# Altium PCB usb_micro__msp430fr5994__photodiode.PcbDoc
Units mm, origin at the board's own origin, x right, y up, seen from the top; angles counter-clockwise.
Board outline 40 x 21 mm, 2 copper layers (Top, Bottom), stack 0 mm thick; 25 components, 16 nets, 136 pads, 47 vias.
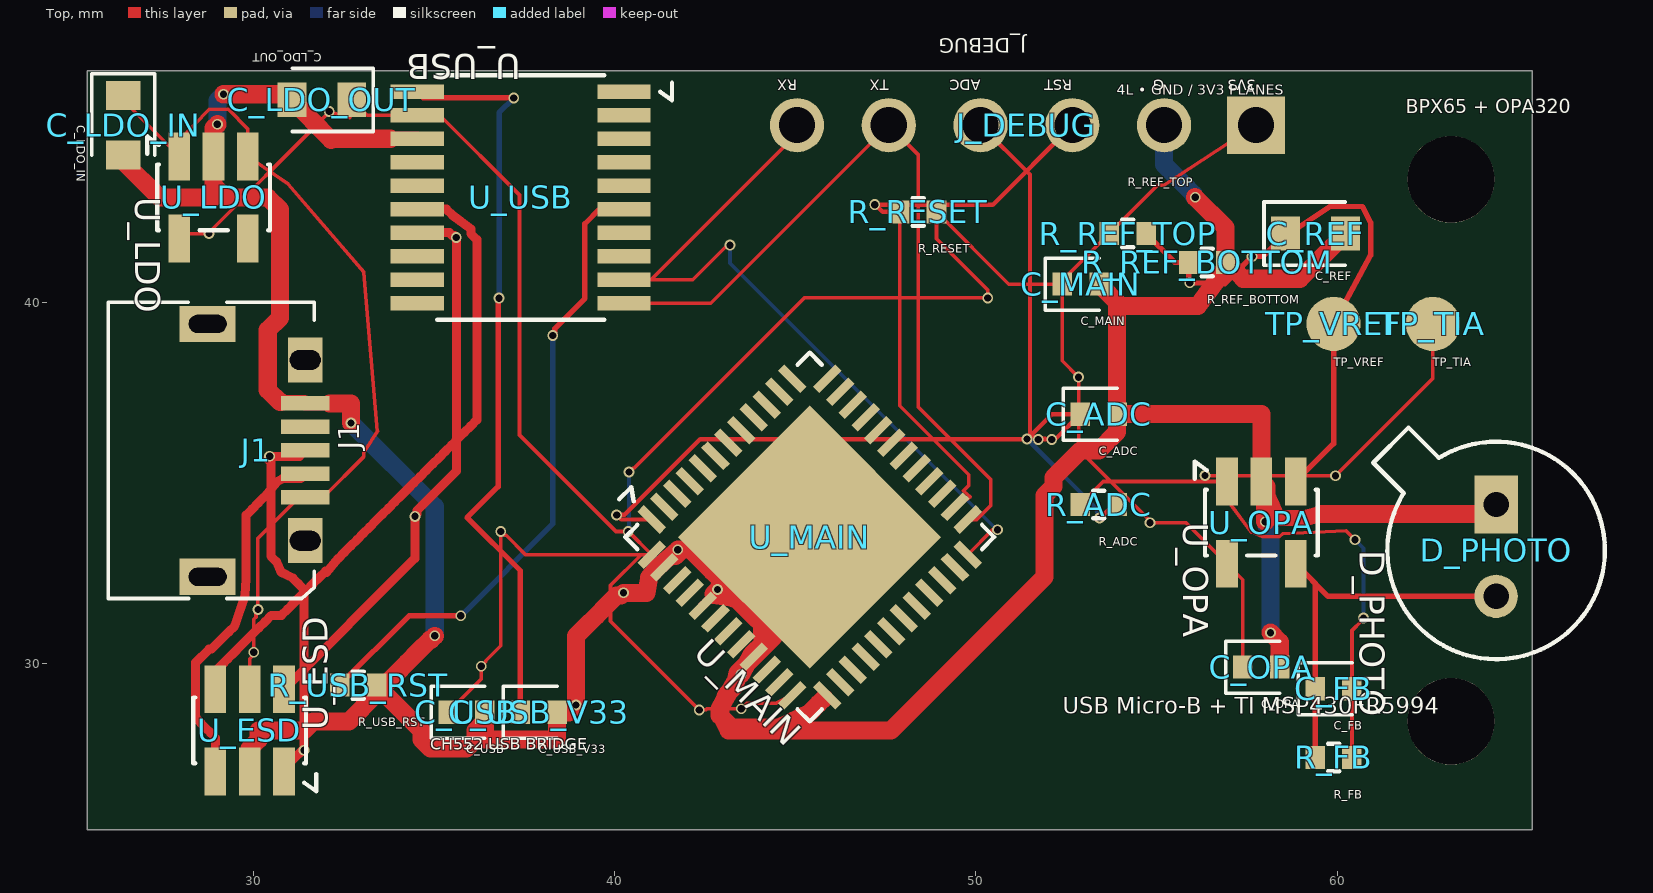
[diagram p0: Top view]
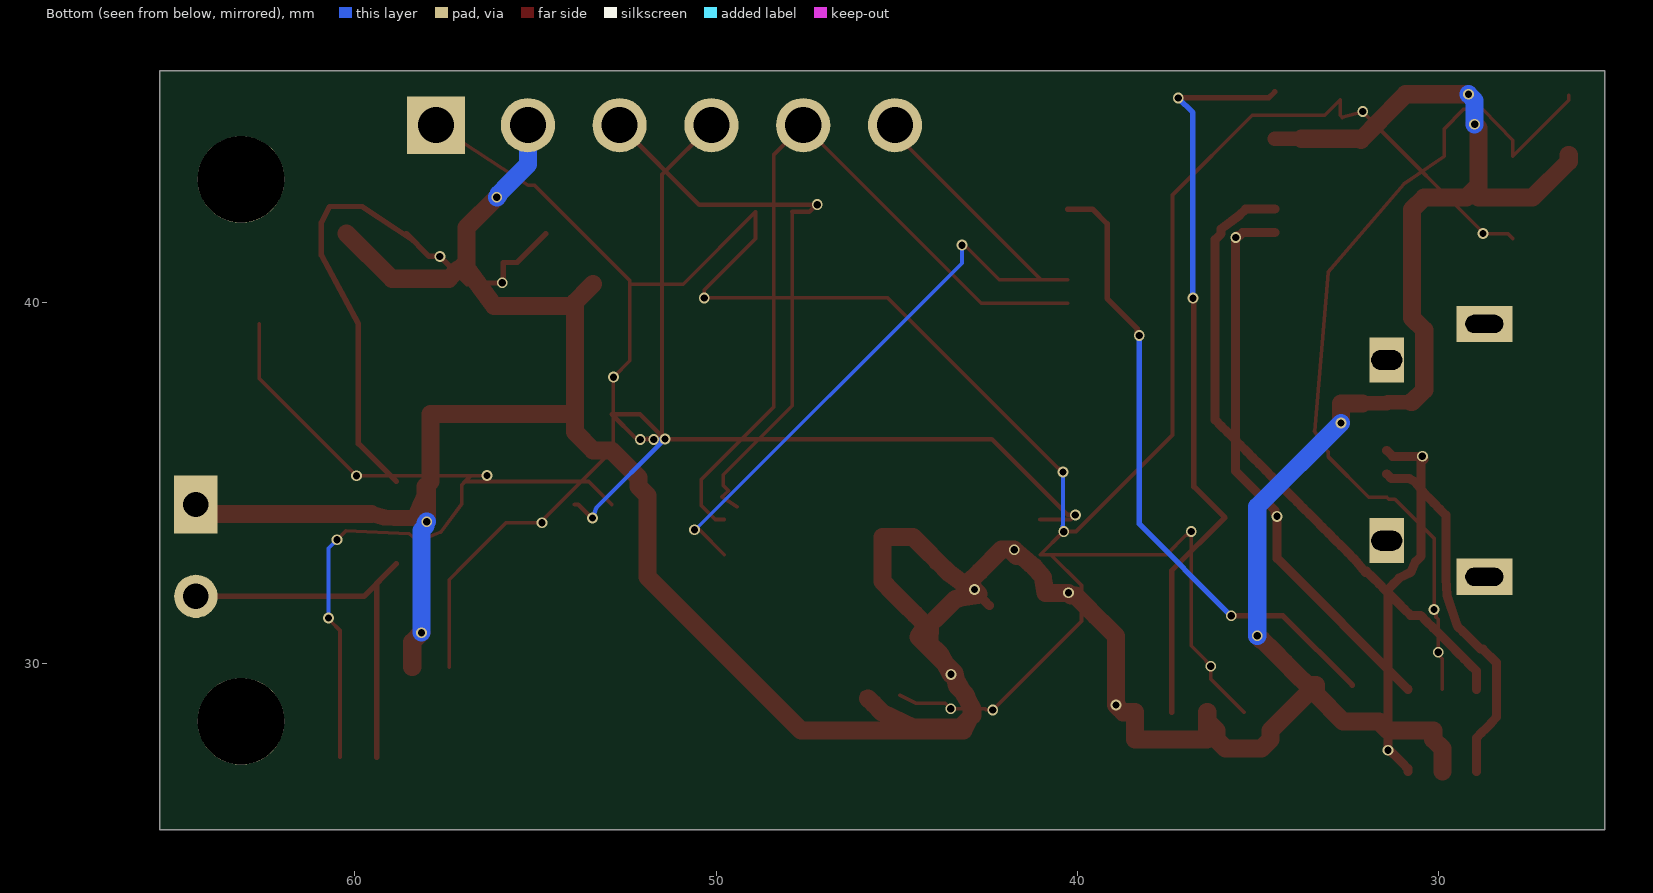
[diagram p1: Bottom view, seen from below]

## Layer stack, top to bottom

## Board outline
25.4,46.4 65.4,46.4 65.4,25.4 25.4,25.4

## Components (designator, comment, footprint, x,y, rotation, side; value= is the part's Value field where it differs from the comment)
C_ADC "" TSCIRCUIT-1.5600x0.6400mm 53.4,36.9 r0 top
C_FB "" TSCIRCUIT-1.5600x0.6400mm 59.9,29.3 r0 top
C_LDO_IN "" TSCIRCUIT-0.9500x2.4500mm 26.4,44.9 r270 top
C_LDO_OUT "" TSCIRCUIT-2.4500x0.9500mm 31.9,45.6 r180 top
C_MAIN "" TSCIRCUIT-1.5600x0.6400mm 52.9,40.5 r0 top
C_OPA "" TSCIRCUIT-1.5600x0.6400mm 57.9,29.9 r0 top
C_REF "" TSCIRCUIT-2.4500x0.9500mm 59.4,41.9 r0 top
C_USB "" TSCIRCUIT-1.5600x0.6400mm 35.9,28.65 r0 top
C_USB_V33 "" TSCIRCUIT-1.5600x0.6400mm 37.9,28.65 r0 top
D_PHOTO "" TSCIRCUIT-1.2000x3.9400mm 64.4,33.23 r270 top
J1 "" TSCIRCUIT-4.1500x8mm 30.037,35.9 r90 top
J_DEBUG "" TSCIRCUIT-14.2000x1.5000mm 51.4,44.9 r180 top
R_ADC "" TSCIRCUIT-1.5600x0.6400mm 53.4,34.4 r0 top
R_FB "" TSCIRCUIT-1.5600x0.6400mm 59.9,27.4 r0 top
R_REF_BOTTOM "" TSCIRCUIT-1.5600x0.6400mm 56.4,41.1 r0 top
R_REF_TOP "" TSCIRCUIT-1.5600x0.6400mm 54.2,41.9 r0 top
R_RESET "" TSCIRCUIT-1.5600x0.6400mm 48.4,42.5 r0 top
R_USB_RST "" TSCIRCUIT-1.5600x0.6400mm 32.9,29.4 r0 top
TP_TIA "" TSCIRCUIT-1.5000x1.5000mm 62.65,39.4 r0 top
TP_VREF "" TSCIRCUIT-1.5000x1.5000mm 59.9,39.4 r0 top
U_ESD "" TSCIRCUIT-2.5000x3.6000mm#1 29.9,28.15 r90 top
U_LDO "" TSCIRCUIT-2.5000x3.6000mm#2 28.9,42.9 r270 top
U_MAIN "" TSCIRCUIT-9.5459x9.5459mm 45.4,33.5 r315 top
U_OPA "" TSCIRCUIT-2.5000x3.6000mm#2 57.9,33.9 r270 top
U_USB "" TSCIRCUIT-7.2000x6.2500mm 37.4,42.9 r180 top

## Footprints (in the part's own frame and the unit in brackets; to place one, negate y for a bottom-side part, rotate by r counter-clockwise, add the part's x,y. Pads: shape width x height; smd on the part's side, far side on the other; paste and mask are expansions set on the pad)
TSCIRCUIT-0.9500x2.4500mm [mm]
  rect 0.8x0.95 smd: 1(-0.825,0) 2(0.825,0)
  silkscreen extent -1.43,-0.87 0.82,0.87
TSCIRCUIT-1.2000x3.9400mm [mm]
  rect 1.6x1.2 hole 0.7: 1(-1.17,0)
  round 1.2 hole 0.7: 2(1.37,0)
  silkscreen extent -3.3,-3.4 3.11,3.01
TSCIRCUIT-1.5000x1.5000mm [mm]
  round 1.5 smd: 1(0,0)
TSCIRCUIT-1.5600x0.6400mm [mm]
  rect 0.54x0.64 smd: 1(-0.51,0) 2(0.51,0)
  silkscreen extent -0.98,-0.72 0.51,0.72
TSCIRCUIT-2.4500x0.9500mm [mm]
  rect 0.8x0.95 smd: 1(-0.825,0) 2(0.825,0)
  silkscreen extent -1.43,-0.87 0.82,0.87
TSCIRCUIT-2.5000x3.6000mm#1 [mm]
  rect 1.325x0.6 smd: 1(-1.137,-0.95) 2(-1.137,0) 3(-1.137,0.95) 4(1.138,0.95) 5(1.138,0) 6(1.138,-0.95)
  silkscreen extent -1.69,-1.84 0.91,1.56
TSCIRCUIT-2.5000x3.6000mm#2 [mm]
  rect 1.325x0.6 smd: 1(-1.137,-0.95) 2(-1.137,0) 3(-1.137,0.95) 4(1.138,0.95) 5(1.138,-0.95)
  silkscreen extent -1.69,-1.84 0.91,1.56
TSCIRCUIT-4.1500x8mm [mm]
  rect 0.4x1.35 smd: 1(-1.301,-1.4) 2(-0.65,-1.4) 3(0,-1.4) 4(0.65,-1.4) 5(1.3,-1.4)
  rect 1.25x0.95 hole 0.55 slot 0.85 at 90 deg: 6(2.5,-1.4) 7(-2.5,-1.4)
  rect 1x1.55 hole 0.5 slot 1.05 at 90 deg: 8(-3.5,1.3) 9(3.5,1.3)
  silkscreen extent -4.1,-1.65 4.1,4.05
TSCIRCUIT-7.2000x6.2500mm [mm]
  rect 1.475x0.4 smd: 1(-2.863,-2.925) 2(-2.863,-2.275) 3(-2.863,-1.625) 4(-2.863,-0.975) 5(-2.863,-0.325) 6(-2.863,0.325) 7(-2.863,0.975) 8(-2.863,1.625) 9(-2.863,2.275) 10(-2.863,2.925) 11(2.862,2.925) 12(2.862,2.275) 13(2.862,1.625) 14(2.862,0.975) 15(2.862,0.325) 16(2.862,-0.325) 17(2.862,-0.975) 18(2.862,-1.625) 19(2.862,-2.275) 20(2.862,-2.925)
  silkscreen extent -4.19,-3.38 2.31,3.38
TSCIRCUIT-9.5459x9.5459mm [mm]
  rect 0.875x0.25 smd: 1(-3.438,-2.75) 2(-3.438,-2.25) 3(-3.438,-1.75) 4(-3.438,-1.25) 5(-3.438,-0.75) 6(-3.438,-0.25) 7(-3.438,0.25) 8(-3.438,0.75) 9(-3.438,1.25) 10(-3.438,1.75) 11(-3.438,2.25) 12(-3.438,2.75) 25(3.438,2.75) 26(3.437,2.25) 27(3.437,1.75) 28(3.437,1.25) 29(3.438,0.75) 30(3.437,0.25) 31(3.437,-0.25) 32(3.437,-0.75) 33(3.438,-1.25) 34(3.437,-1.75) 35(3.437,-2.25) 36(3.437,-2.75)
  rect 0.25x0.875 smd: 13(-2.75,3.438) 14(-2.25,3.438) 15(-1.75,3.438) 16(-1.25,3.438) 17(-0.75,3.438) 18(-0.25,3.438) 19(0.25,3.438) 20(0.75,3.438) 21(1.25,3.438) 22(1.75,3.438) 23(2.25,3.438) 24(2.75,3.438) 37(2.75,-3.437) 38(2.25,-3.438) 39(1.75,-3.438) 40(1.25,-3.438) 41(0.75,-3.437) 42(0.25,-3.438) 43(-0.25,-3.438) 44(-0.75,-3.438) 45(-1.25,-3.437) 46(-1.75,-3.438) 47(-2.25,-3.438) 48(-2.75,-3.438)
  rect 5.15x5.15 smd: 49(0,0)
  silkscreen extent -4.47,-3.61 3.61,3.61
TSCIRCUIT-14.2000x1.5000mm [mm]
  rect 1.6x1.6 hole 1: 1(-6.35,0)
  round 1.5 hole 1: 2(-3.81,0) 3(-1.27,0) 4(1.27,0) 5(3.81,0) 6(6.35,0)

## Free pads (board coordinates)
  round 2.4 hole 2.4 unplated: NPTH-1(63.15,43.4) NPTH-2(63.15,28.4)

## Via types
v1: diameter 0.3, hole 0.2, Top to Bottom, 47 vias

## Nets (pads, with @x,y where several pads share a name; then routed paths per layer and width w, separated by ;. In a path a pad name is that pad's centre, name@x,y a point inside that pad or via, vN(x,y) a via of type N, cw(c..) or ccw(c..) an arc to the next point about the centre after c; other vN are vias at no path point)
".U_USB > .pin9 to .U_MAIN > .pin25": J_DEBUG.6 U_MAIN.25 U_USB.9 | length 22.1
  Top w0.1: v1(43.195,41.579) 43.193,41.577 43.118,41.577 42.166,40.625 U_USB.9 40.269,40.619 41.005,40.619 45.05,44.664 J_DEBUG.6 ; U_MAIN.25 50.461,33.7 v1(50.6,33.7)
  Bottom w0.1: v1(43.195,41.579) 43.195,41.081 50.576,33.7 v1(50.6,33.7)
".U_USB > .pin10 to .U_MAIN > .pin24": J_DEBUG.5 U_MAIN.24 U_USB.10 | length 21.9
  Top w0.1: U_USB.10 42.665,39.975 J_DEBUG.5 48.4,44.09 48.4,42.236 48.4,37.11 50.407,35.103 50.407,34.368 50.025,33.986 U_MAIN.24@49.775,33.986
ADC_IN: C_ADC.1 J_DEBUG.4 R_ADC.2 U_MAIN.1 | length 31.5
  Top w0.12: U_MAIN.1 40.18,33.986 v1(40.057,34.109) 40.065,34.117 40.275,34.117 42.368,36.21 v1(51.416,36.21) 51.423,36.218 52.106,36.9 C_ADC.1 ; J_DEBUG.4 51.496,43.534 51.496,36.416 51.496,36.291 v1(52.1,36.2) v1@52.2,36.21 ; v1(51.725,36.2) v1@52.2,36.21 ; v1(53.42,34.028) 53.394,34.086 53.399,34.007 53.399,33.983 53.817,34.4 R_ADC.2 ; v1@52.2,36.21 C_ADC.1 ; v1@52.2,36.21 C_ADC.1
  Bottom w0.12: v1(51.725,36.2) 51.422,36.204 53.31,34.317 v1(53.42,34.028)
GND: C_ADC.2 C_LDO_IN.2 C_LDO_OUT.2 C_MAIN.2 C_OPA.2 C_REF.2 C_USB.2 C_USB_V33.2 D_PHOTO.1 J1.5 J_DEBUG.2 R_REF_BOTTOM.2 R_USB_RST.2 U_ESD.2 U_LDO.2 U_MAIN.36 U_MAIN.40 U_MAIN.44 U_MAIN.47 U_MAIN.49 U_OPA.2 U_USB.18 | length 127.1
  Top w0.1: v1(43.5,29.7) U_MAIN.40
  Top w0.2: U_MAIN.47 v1(41.75,33.15)
  Top w0.25: U_MAIN.47 41.688,32.97 ; U_MAIN.44@42.733,31.894 U_MAIN.44 ; 42.734,31.923 U_MAIN.44 ; 42.748,31.909 U_MAIN.44 ; U_MAIN.40@43.568,29.9 U_MAIN.40 ; 45.798,29.036 U_MAIN.36
  Top w0.381: U_MAIN.44@42.733,31.894 42.733,31.9 42.747,31.91
  Top w0.4: J1.5@30.763,37.233 31.405,37.233 J1.5 J1.5@32.113,37.2 ; U_USB.18@33.8,44.525 U_USB.18
  Top w0.45: U_OPA.2@58.046,34.7 58.192,34.362 58.338,34.025 58.619,34.025 58.9,34.025 59.181,34.041 59.544,34.141
  Top w0.471: U_MAIN.40@43.55,29.87 U_MAIN.40@43.567,29.9
  Top w0.5: C_LDO_IN.2 26.4,43.9 27.4,42.9 28.4,42.9 28.9,42.9 U_LDO.2 ; v1(29.005,44.925) 28.9,44.82 U_LDO.2 ; v1(29.175,45.756) 30.919,45.756 C_LDO_OUT.2 32.15,44.495 32.18,44.525 33.8,44.525 ; U_ESD.2 29.9,27.65 30.15,27.9 30.15,28.15 31.4,28.15 31.65,28.4 32.65,28.4 33.4,29.15 33.4,29.4 R_USB_RST.2 ; J1.5@30.763,37.233 30.733,37.233 30.4,37.567 30.4,39.233 30.733,39.567 30.733,42.567 30.4,42.9 29.233,42.9 28.9,43.233 28.9,43.9 U_LDO.2 ; 32.113,37.2 32.707,37.2 v1(32.707,36.66) ; v1(35.022,30.766) 34.914,30.658 34.889,30.658 34.574,30.344 34.26,30.029 33.945,29.715 33.631,29.4 R_USB_RST.2 ; 41.688,32.97 41.868,33.15 41.9,33.15 42.098,33.15 42.702,32.546 43.025,32.223 43.025,32.15 42.989,32.15 42.748,31.909 ; v1(41.75,33.15) 41.2,32.678 40.957,32.384 40.882,31.957 40.563,31.957 v1(40.243,31.957) 40.17,31.884 40.058,31.884 39.776,31.602 39.495,31.321 39.213,31.039 38.932,30.758 38.932,30.281 38.932,29.804 38.932,29.328 v1(38.932,28.851) 38.857,28.776 38.731,28.65 C_USB_V33.2 38.41,27.9 36.41,27.9 C_USB.2 36.4,28.65 36.4,28.4 36.15,28.15 36.15,27.9 35.9,27.65 34.9,27.65 34.65,27.9 34.65,28.15 33.41,29.39 R_USB_RST.2 ; 42.734,31.923 v1(42.85,32.05) 42.753,31.894 43.023,31.85 43.292,31.805 43.369,31.79 43.608,31.551 43.847,31.311 44.086,31.072 44.086,30.908 44.102,30.563 43.806,30.26 v1(43.5,29.7) ; 42.747,31.91 43.094,32.164 43.545,32.494 43.88,32.829 44.216,33.165 44.551,33.5 44.975,33.5 U_MAIN.49 45.4,33.088 45.4,32.677 45.4,32.265 45.099,31.964 44.799,31.664 44.498,31.363 44.198,31.063 44.4,30.733 43.4,29.733 43.333,29.378 43.092,29.137 42.9,28.65 43.15,28.15 47.65,28.15 49.32,29.82 51.9,32.4 51.9,34.65 52.15,34.9 52.15,35.15 52.9,35.9 53.4,35.9 53.91,36.41 C_ADC.2 ; 43.55,29.87 42.9,28.733 42.9,28.567 43.233,28.233 44.567,28.233 45.408,28.647 45.647,28.886 45.798,29.036 ; v1(56.07,42.906) 56.91,42.066 R_REF_BOTTOM.2 ; v1(58.009,33.925) 58.009,34.929 U_OPA.2 ; U_OPA.2@58.046,34.7 58.046,34.892 U_OPA.2 ; v1(58.157,30.853) 58.41,30.6 C_OPA.2 ; 59.544,34.141 60.004,34.141 60.464,34.141 60.923,34.141 61.383,34.141 61.843,34.141 62.302,34.141 62.762,34.141 63.222,34.141 63.681,34.141 64.141,34.141 D_PHOTO.1 ; C_REF.2 58.975,40.65 57.4,40.65 57.15,40.9 57.11,40.9 R_REF_BOTTOM.2 ; C_ADC.2 53.91,40 C_MAIN.2 54.01,39.9 56.15,39.9 56.921,40.963 R_REF_BOTTOM.2 ; C_ADC.2 57.9,36.9 U_OPA.2
  Bottom w0.5: v1(29.005,44.925) 29.005,45.586 v1(29.175,45.756) ; v1(32.707,36.66) 35.022,34.346 v1(35.022,30.766) ; J_DEBUG.2 55.21,44.535 55.21,44.171 55.21,43.806 55.482,43.534 55.755,43.261 56.027,42.989 56.027,42.949 v1(56.07,42.906) ; v1(58.009,33.925) 58.04,33.894 58.04,33.804 58.157,33.687 58.157,33.215 58.157,32.742 58.157,32.27 58.157,31.798 58.157,31.325 v1(58.157,30.853)
MAIN_RESET: J_DEBUG.3 R_RESET.1 U_MAIN.23 | length 16.5
  Top w0.1: R_RESET.1 47.89,37.131 49.8,35.221 49.8,34.925 49.656,34.781 49.842,34.615 U_MAIN.23
  Top w0.12: v1(47.2,42.7) 50.47,42.7 J_DEBUG.3 ; v1(47.2,42.7) 47.223,42.699 47.422,42.5 R_RESET.1
PD_SUM: C_FB.1 D_PHOTO.2 R_FB.1 U_OPA.4 | length 11.5
  Top w0.15: R_FB.1 C_FB.1 59.39,32.222 U_OPA.4 59.752,31.86 D_PHOTO.2
TIA_OUT: C_FB.2 R_ADC.1 R_FB.2 TP_TIA.1 U_OPA.1 | length 24.8
  Top w0.1: R_ADC.1 53.528,35.037 U_OPA.1 ; v1(56.342,35.2) 56.453,35.2 56.456,35.196 v1(59.95,35.196) 60.002,35.248 62.65,37.896 TP_TIA.1 ; v1(56.342,35.2) 56.787,35.2 U_OPA.1 ; R_FB.2 C_FB.2 60.41,30.913 60.684,31.187 60.684,31.213 v1(60.73,31.259) ; v1(60.493,33.425) 60.248,33.67 58.493,33.591 58.392,33.509 58.172,33.51 58.168,33.51 57.946,33.51 57.62,33.639 57.045,34.412 57.045,34.942 U_OPA.1
  Bottom w0.1: v1(60.493,33.425) 60.505,33.413 60.73,33.188 v1(60.73,31.259)
USB_BRIDGE_RESET: R_USB_RST.1 U_USB.6 | length 17.7
  Top w0.15: R_USB_RST.1 34.311,31.321 v1(35.743,31.321) ; v1(38.287,39.079) 38.345,39.137 38.345,39.268 39.179,40.103 39.179,42.172 39.582,42.575 U_USB.6
  Bottom w0.15: v1(35.743,31.321) 35.799,31.377 38.287,33.865 v1(38.287,39.079)
USB_BRIDGE_V33: C_USB_V33.1 U_USB.20 | length 20.9
  Top w0.15: U_USB.20 34.707,45.656 v1(37.208,45.656) ; v1(36.804,40.112) 36.775,40.083 36.775,39.916 36.775,34.897 35.917,34.04 37.39,32.567 C_USB_V33.1
  Bottom w0.15: v1(36.804,40.112) 36.804,45.25 37.209,45.655 v1(37.208,45.656)
USB_DM_MCU: U_ESD.4 U_USB.15 | length 17.7
  Top w0.25: U_ESD.4@28.95,29.287 28.95,29.537 28.95,29.786 29.122,29.958 29.294,30.13 29.466,30.302 29.638,30.474 29.809,30.646 29.981,30.818 30.153,30.989 30.325,31.161 30.497,31.333 30.637,31.333 30.777,31.333 30.951,31.508 31.126,31.682 31.3,31.857 31.475,32.032 31.65,32.206 31.824,32.381 31.999,32.555 32.025,32.525 32.348,32.904 32.522,33.079 32.697,33.254 32.872,33.428 33.046,33.603 33.221,33.777 33.395,33.952 33.57,34.127 33.744,34.301 33.919,34.476 34.094,34.65 34.268,34.825 34.443,34.999 34.617,35.174 34.792,35.349 34.966,35.523 35.141,35.698 35.316,35.872 35.49,36.047 35.665,36.221 35.839,36.396 36.014,36.571 36.189,36.745 36.189,36.995 36.189,37.244 36.189,37.493 36.189,37.743 36.189,37.992 36.189,38.241 36.189,38.491 36.189,38.74 36.189,38.99 36.189,39.239 36.189,39.488 36.189,39.738 36.189,39.987 36.189,40.236 36.189,40.486 36.189,40.735 36.189,40.985 36.189,41.234 36.189,41.483 36.189,41.733 36.02,41.901 36.025,42.025 35.515,42.407 35.346,42.575 35.144,42.575 34.942,42.575 34.74,42.575 U_USB.15
USB_DM_PORT: J1.2 U_ESD.3 | length 10
  Top w0.25: U_ESD.3 28.95,27.245 28.95,27.478 28.95,27.711 28.95,27.944 28.816,28.078 28.682,28.212 28.548,28.346 28.4,28.525 28.4,30.025 28.775,30.4 28.849,30.404 29.007,30.562 29.166,30.72 29.324,30.879 29.482,31.037 29.775,31.9 29.799,32.332 29.799,32.576 29.799,32.821 29.799,33.065 29.799,33.31 29.799,33.554 29.799,33.798 29.799,34.043 29.799,34.105 29.968,34.274 30.138,34.443 30.307,34.613 30.65,35.025 30.815,35.121 31.062,35.121 31.309,35.121 J1.2
USB_DP_MCU: U_ESD.6 U_USB.14 | length 15.6
  Top w0.25: U_ESD.6 34.474,32.911 v1(34.474,34.073) 34.533,34.132 34.533,34.241 35.619,35.327 v1(35.619,41.79) 35.562,41.847 35.505,41.847 35.427,41.925 U_USB.14
USB_DP_PORT: J1.3 U_ESD.1 | length 10.5
  Top w0.25: U_ESD.1 30.85,27.091 31.008,27.249 31.166,27.407 31.324,27.565 31.365,27.565 v1(31.4,27.6) 31.4,27.848 31.4,28.096 31.4,28.343 31.4,28.591 31.4,28.839 31.4,29.087 31.4,29.335 31.4,29.582 31.4,29.83 31.4,30.078 31.4,30.326 31.4,30.574 31.4,30.821 31.4,31.069 31.4,31.317 31.4,31.565 31.4,31.813 31.4,32.06 31.248,32.212 31.096,32.364 30.775,32.525 30.641,32.82 30.489,32.972 30.489,33.207 30.489,33.443 30.489,33.679 30.489,33.915 30.489,34.151 30.489,34.387 30.489,34.623 30.489,34.859 30.489,35.095 30.489,35.331 30.489,35.566 30.403,35.652 30.403,35.686 v1(30.452,35.735) 30.657,35.735 30.863,35.735 31.068,35.735 31.273,35.735 J1.3
VBUS5: C_LDO_IN.1 J1.1 U_ESD.5 U_LDO.1 U_LDO.3 | length 24
  Top w0.1: C_LDO_IN.1 26.4,45.588 U_LDO.1 27.95,44.486 28.782,45.343 29.319,45.336 29.85,44.787 U_LDO.3 30.967,43.27 33.062,40.826 33.436,36.426 33.062,35.853 33.062,35.732 31.935,34.605 31.444,34.605 J1.1 31.382,34.544 31.212,34.544 30.126,33.459 v1(30.126,31.496) 30.076,31.446 30.076,31.284 30.013,31.221 v1(30.013,30.311) 30.009,30.307 30.009,30.242 29.9,30.134 U_ESD.5
VCC_3V3: C_LDO_OUT.1 C_MAIN.1 C_OPA.1 C_USB.1 J_DEBUG.1 R_REF_TOP.1 R_RESET.2 U_LDO.5 U_MAIN.37 U_MAIN.48 U_OPA.5 U_USB.19 | length 84.9
  Top w0.1: U_LDO.5 28.088,41.9 v1(28.77,41.9) 28.834,41.964 28.834,41.992 31.816,44.974 v1(32.1,45.275) 32.672,45.113 32.672,45.122 32.725,45.174 C_LDO_OUT.1 33.15,45.175 U_USB.19 35.163,45.175 37.368,42.97 37.368,36.324 40.04,33.652 40.387,33.652 U_MAIN.48 ; C_USB.1 36.31,29.57 v1(36.31,29.925) 36.432,30.047 36.432,30.076 36.848,30.492 v1(36.848,33.653) 36.951,33.55 36.997,33.55 37.533,33.014 U_MAIN.48 ; v1(40.38,33.649) 40.39,33.649 U_MAIN.48 ; v1(40.4,35.3) 40.501,35.401 40.534,35.401 45.252,40.119 v1(50.329,40.119) 50.327,40.121 50.327,40.337 48.91,41.755 R_RESET.2 50.91,40.5 C_MAIN.1 ; U_MAIN.37 44.472,28.899 43.658,28.899 43.527,28.768 v1(43.506,28.747) 42.552,28.747 42.521,28.715 v1(42.341,28.714) v1(42.341,28.714) 39.888,31.167 39.888,32.166 40.735,33.014 U_MAIN.48 ; C_OPA.1 57.39,32.322 U_OPA.5 55.818,33.894 v1(54.821,33.894) 54.757,33.958 54.757,34.016 52.843,35.93 v1(52.843,37.926) 52.823,37.946 52.39,38.379 C_MAIN.1 ; J_DEBUG.1 55.19,43.235 55.025,43.235 R_REF_TOP.1 52.39,40.6 C_MAIN.1
  Bottom w0.1: v1(40.38,33.649) 40.415,33.684 40.415,33.809 40.4,33.823 v1(40.4,35.3)
VREF_0V5: C_REF.1 R_REF_BOTTOM.1 R_REF_TOP.2 TP_VREF.1 U_OPA.3 | length 16.5
  Top w0.15: R_REF_TOP.2 55.51,41.1 R_REF_BOTTOM.1 55.89,40.609 55.896,40.603 55.896,40.56 v1(55.918,40.538) 56.886,40.508 57.635,41.257 v1(57.647,41.269) 57.944,41.269 C_REF.1 58.392,41.717 59.8,42.65 60.7,42.65 60.925,42.2 60.925,41.3 TP_VREF.1 59.9,36.087 U_OPA.3
pads on no net: J1.4 J1.6 J1.7 J1.8 J1.9 U_LDO.4 U_MAIN.2 U_MAIN.3 U_MAIN.4 U_MAIN.5 U_MAIN.6 U_MAIN.7 U_MAIN.8 U_MAIN.9 U_MAIN.10 U_MAIN.11 U_MAIN.12 U_MAIN.13 U_MAIN.14 U_MAIN.15 U_MAIN.16 U_MAIN.17 U_MAIN.18 U_MAIN.19 U_MAIN.20 U_MAIN.21 U_MAIN.22 U_MAIN.26 U_MAIN.27 U_MAIN.28 U_MAIN.29 U_MAIN.30 U_MAIN.31 U_MAIN.32 U_MAIN.33 U_MAIN.34 U_MAIN.35 U_MAIN.38 U_MAIN.39 U_MAIN.41 U_MAIN.42 U_MAIN.43 U_MAIN.45 U_MAIN.46 U_USB.1 U_USB.2 U_USB.3 U_USB.4 U_USB.5 U_USB.7 U_USB.8 U_USB.11 U_USB.12 U_USB.13 U_USB.16 U_USB.17

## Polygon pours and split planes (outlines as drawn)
GND on Mid1 (solid): 65.1,46.1 25.7,46.1 25.7,25.7 65.1,25.7 65.1,31.38 65.001,31.259 64.872,31.153 64.725,31.075 64.566,31.026 64.4,31.01 64.234,31.026 64.075,31.075 63.928,31.153 63.799,31.259 63.693,31.388 63.615,31.535 63.566,31.694 63.55,31.86 63.566,32.026 63.615,32.185 63.693,32.332 63.799,32.461 63.928,32.567 64.075,32.645 64.234,32.694 64.4,32.71 64.566,32.694 64.725,32.645 64.872,32.567 65.001,32.461 65.1,32.34 65.1,33.72 65.001,33.599 64.872,33.493 64.725,33.415 64.566,33.366 64.55,33.365 64.55,33.622 64.63,33.646 64.733,33.701 64.824,33.776 64.899,33.867 64.954,33.97 64.988,34.083 65,34.2 65,34.25 65.1,34.25 65.1,34.55 65,34.55 65,34.6 64.988,34.717 64.954,34.83 64.899,34.933 64.824,35.024 64.733,35.099 64.63,35.154 64.55,35.178 64.55,35.435 64.566,35.434 64.725,35.385 64.872,35.307 65.001,35.201 65.1,35.08
VCC_3V3 on Mid2 (solid): 28.974,46.1 25.7,46.1 25.7,25.7 65.1,25.7 65.1,31.38 65.001,31.259 64.872,31.153 64.725,31.075 64.566,31.026 64.4,31.01 64.234,31.026 64.075,31.075 63.928,31.153 63.799,31.259 63.693,31.388 63.615,31.535 63.566,31.694 63.55,31.86 63.566,32.026 63.615,32.185 63.693,32.332 63.799,32.461 63.928,32.567 64.075,32.645 64.234,32.694 64.4,32.71 64.566,32.694 64.725,32.645 64.872,32.567 65.001,32.461 65.1,32.34 65.1,33.72 65.001,33.599 64.872,33.493 64.725,33.415 64.566,33.366 64.4,33.35 64.234,33.366 64.075,33.415 63.928,33.493 63.799,33.599 63.693,33.728 63.615,33.875 63.566,34.034 63.55,34.2 63.55,34.6 63.566,34.766 63.615,34.925 63.693,35.072 63.799,35.201 63.928,35.307 64.075,35.385 64.234,35.434 64.4,35.45 64.566,35.434 64.725,35.385 64.872,35.307 65.001,35.201 65.1,35.08 65.1,46.1 29.376,46.1 29.397,46.089 29.458,46.039 29.508,45.978 29.545,45.909 29.567,45.834 29.575,45.756 29.567,45.678 29.545,45.603 29.508,45.534 29.458,45.473 29.397,45.423 29.328,45.386 29.253,45.364 29.175,45.356 29.097,45.364 29.022,45.386 28.953,45.423 28.892,45.473 28.842,45.534 28.805,45.603 28.783,45.678 28.775,45.756 28.783,45.834 28.805,45.909 28.842,45.978 28.892,46.039 28.953,46.089

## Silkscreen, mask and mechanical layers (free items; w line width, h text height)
Top Overlay:
  text "4L • GND / 3V3 PLANES" at 53.9,45.65 h0.48
  text "BPX65 + OPA320" at 61.9,45.1 h0.65
  text "USB Micro-B + TI MSP430FR5994" at 52.4,28.45 h0.78
  text "CH552 USB BRIDGE" at 34.9,27.5 h0.55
